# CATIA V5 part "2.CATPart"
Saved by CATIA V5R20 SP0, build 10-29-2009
Part number: 2
Bounding box of the stored display mesh (mm): x -35 to 35, y -1.132 to 135, z -0.104 to 70
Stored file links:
  E:\Ehsan\Amoozesh\CATIA\CATIA Course\Advanced\Videos\Session-18\2.CATPart
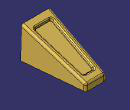
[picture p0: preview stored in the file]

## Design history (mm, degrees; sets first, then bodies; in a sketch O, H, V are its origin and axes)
Set1
  Plane1: type Offset, RefPlane zx-plane, Offset 135
  Sketch1 on Plane1, origin (0, 135, 0), H (-1, 0, 0), V (0, 0, 1)
    point P1 (-22.5, 0)
    line L1 (-22.5, 0) -> (-22.5, 15)
    line L2 (-22.5, 15) -> (22.5, 15)
    line L3 (22.5, 15) -> (22.5, 0)
    point P4 (22.5, 0)
    length L2 = 45
    distance L2 H = 15
    coincidence: P1 H, P4 H
    vertical: L1 V, L3 V
    horizontal: L2 H
    symmetry: L3 L1 V
  Loft1: Sections (Sketch3; Sketch1), SectionCouplingPoints ({coupling CouplingPoints (vertex [element of Sketch3 | element of Sketch3]; vertex [element of Sketch1 | element of Sketch1])}; {coupling CouplingPoints (vertex [element of Sketch3 | element of Sketch3]; vertex [element of Sketch1 | element of Sketch1])})
  Fill1: Boundary (Sketch1; {line type PtPt, FirstPoint Sketch1.P1, SecondPoint Sketch1.P4})
  Sketch2 on face of Loft1, origin (0, 24.4588, 60.0353), H (1, 0, 0), V (0, -0.9261, 0.3773)
    line L1 (13.5109, -104.363) -> (21.4971, 11.4108)
    line L2 (21.4971, 11.4108) -> (-21.4971, 11.4108)
    line L3 (-21.4971, 11.4108) -> (-13.5109, -104.363)
    line L4 (-13.5109, -104.363) -> (13.5109, -104.363)
    reference projected line E1 (-32.5555, 26.4108) -> (32.5555, 26.4108) from Sketch3.L2
    reference projected line E2 (-22.5, -119.363) -> (22.5, -119.363) from Sketch1.L2
    reference projected line E3 (-32.5555, 26.4108) -> (-22.5, -119.363) from edge [face of Loft1 | face of Loft1]
    reference projected line E4 (-32.5555, 26.4108) -> (-22.5, -119.363) from edge [face of Loft1 | face of Loft1]
    distance L2 E1 = 15
    distance L4 E2 = 15
    distance L3 E4 = 10
    horizontal: L4 H, L2 H
    symmetry: L3 L1 V
    parallelism: L3 E3
  Split1: ToCut Loft1, Cutting Sketch2
  Sweep1: type Segment, GuideCrv Sketch2, GuideSurf Split1, Length1 5, Length2 0, Angle 60
  Fill2: Boundary (edge of Sweep1; edge of Sweep1; edge of Sweep1; edge of Sweep1)
  Join1: Elements (Split1; Fill1; Sweep1; Fill2)
  Fillet1: radius 5, on edge [face of Loft1 | face of Loft1] (x2); edge [face of Loft1 | face of Fill1] (x3); edge [face of Sweep1 | face of Sweep1] (x4)
  Fillet2: radius 1, on face of Fill2
  Fillet3: radius 3, on edge [face of Loft1 | face of Sweep1]
  ThickSurface1: Surface Fillet3, TopOffset 3, BotOffset 0
Body1 (main body)
  Sketch3 on zx-plane, origin (0, 0, 0), H (-1, 0, 0), V (0, 0, 1)
    point P1 (-35, 0)
    line L1 (-35, 0) -> (-32.5555, 70)
    point P2 (-32.5555, 70)
    line L2 (-32.5555, 70) -> (32.5555, 70)
    point P3 (32.5555, 70)
    line L3 (32.5555, 70) -> (35, 0)
    point P4 (35, 0)
    distance L2 H = 70
    distance P4 P1 = 70
    angle V L1 = 2
    coincidence: P1 H, P4 H
    horizontal: L2 H
    symmetry: P4 P1 V, P3 P2 V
